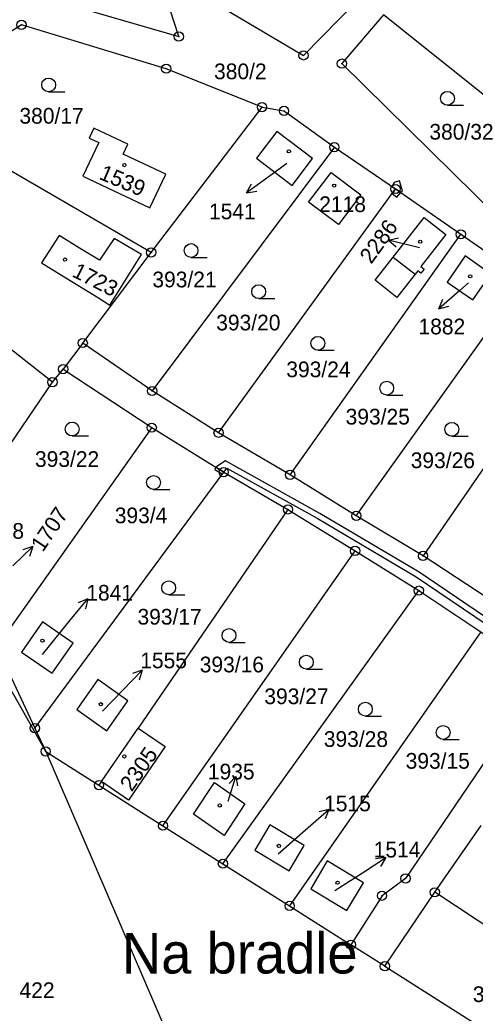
# Model space of a CAD drawing. Extents: x -680203 to -673936, y -1102717 to -1093650.
# Drawn here: x -679915.5 to -679866.3, y -1098047.4 to -1097939.8 of the extents above; entities that cross this region are included whole.
import ezdxf

# ---------------------------------------------------------------- set-up
doc = ezdxf.new("R2010")
doc.units = 0
for name, color, linetype in [('SOxx02xx_Koleje_param další_Popis10', 7, 'Continuous'), ('SOxx02xx_Staničení_Popis10', 7, 'Continuous'), ('SOxxxxxx_Koleje_hlavní_body_Popis10', 7, 'Continuous'), ('SOxxxxxx_Koleje_LN_parametry_Popis10', 7, 'Continuous'), ('SOxxxxxx_Koleje_param další_Popis10', 7, 'Continuous'), ('SOxxxxxx_Osa_bod_P', 7, 'Continuous'), ('SOxxxxxx_Staničení_Popis10', 7, 'Continuous'), ('x_prac', 7, 'Continuous')]:
    doc.layers.add(name, color=color, linetype=linetype)

msp = doc.modelspace()

# ---------------------------------------------------------------- linework, layer by layer
at = {"layer": 'SOxx02xx_Koleje_param další_Popis10'}
for centre, radius in [((-679915.37, -1097940.37), 0.5), ((-679915.37, -1097940.37), 0.0303), ((-679898.34, -1097941.64), 0.5), ((-679898.34, -1097941.64), 0.0303), ((-679884.84, -1097943.68), 0.5), ((-679884.84, -1097943.68), 0.0303), ((-679880.68, -1097944.57), 0.5), ((-679899.7, -1097945.12), 0.5), ((-679899.7, -1097945.12), 0.0303), ((-679880.68, -1097944.57), 0.0303), ((-679889.33, -1097949.28), 0.5), ((-679889.33, -1097949.28), 0.0303), ((-679886.95, -1097949.69), 0.5), ((-679886.95, -1097949.69), 0.0303), ((-679881.5, -1097953.61), 0.5), ((-679881.5, -1097953.61), 0.0303), ((-679874.87, -1097958.14), 0.5), ((-679874.87, -1097958.14), 0.0303), ((-679867.81, -1097963.05), 0.5), ((-679867.81, -1097963.05), 0.0303), ((-679901.33, -1097965.01), 0.5), ((-679901.33, -1097965.01), 0.0303), ((-679908.74, -1097974.82), 0.5), ((-679908.74, -1097974.82), 0.0303), ((-679910.86, -1097977.64), 0.5), ((-679910.86, -1097977.64), 0.0303), ((-679912.02, -1097979.05), 0.5), ((-679912.02, -1097979.05), 0.0303), ((-679901.22, -1097980.01), 0.5), ((-679901.22, -1097980.01), 0.0303), ((-679901.27, -1097983.98), 0.5), ((-679901.27, -1097983.98), 0.0303), ((-679894.03, -1097984.53), 0.5), ((-679894.03, -1097984.53), 0.0303), ((-679893.48, -1097988.79), 0.5), ((-679893.48, -1097988.79), 0.0303), ((-679886.29, -1097989.08), 0.5), ((-679886.29, -1097989.08), 0.0303), ((-679886.52, -1097992.83), 0.5), ((-679886.52, -1097992.83), 0.0303), ((-679879.12, -1097993.52), 0.5), ((-679879.12, -1097993.52), 0.0303), ((-679879.25, -1097997.32), 0.5), ((-679879.25, -1097997.32), 0.0303), ((-679871.9, -1097997.86), 0.5), ((-679871.9, -1097997.86), 0.0303), ((-679872.35, -1098001.62), 0.5), ((-679872.35, -1098001.62), 0.0303), ((-679913.92, -1098016.51), 0.5), ((-679913.92, -1098016.51), 0.0303), ((-679912.75, -1098019.03), 0.5), ((-679912.75, -1098019.03), 0.0303), ((-679906.98, -1098022.68), 0.5), ((-679906.98, -1098022.68), 0.0303), ((-679900.05, -1098027.07), 0.5), ((-679900.05, -1098027.07), 0.0303), ((-679893.56, -1098031.18), 0.5), ((-679893.56, -1098031.18), 0.0303), ((-679873.8, -1098032.78), 0.5), ((-679873.8, -1098032.78), 0.0303), ((-679876.34, -1098034.65), 0.5), ((-679876.34, -1098034.65), 0.0303), ((-679870.63, -1098034.28), 0.5), ((-679870.63, -1098034.28), 0.0303), ((-679886.34, -1098035.75), 0.5), ((-679886.34, -1098035.75), 0.0303), ((-679879.71, -1098039.95), 0.5), ((-679879.71, -1098039.95), 0.0303), ((-679876.03, -1098042.28), 0.5), ((-679876.03, -1098042.28), 0.0303)]:
    msp.add_circle(centre, radius, dxfattribs=at)
at = {"layer": 'SOxx02xx_Staničení_Popis10'}
for p, q in [((-679886.64, -1097955.38), (-679888.57, -1097956.8)), ((-679888.57, -1097956.8), (-679891, -1097958.56)), ((-679891, -1097958.56), (-679890.48, -1097957.57)), ((-679891, -1097958.56), (-679889.89, -1097958.38)), ((-679875.64, -1097963.67), (-679874.55, -1097963.43)), ((-679872.73, -1097964.4), (-679875.64, -1097963.67)), ((-679875.64, -1097963.67), (-679874.79, -1097964.4)), ((-679872.28, -1097964.52), (-679872.73, -1097964.4)), ((-679866.97, -1097968.32), (-679867.92, -1097969.15)), ((-679867.92, -1097969.15), (-679870.19, -1097971.12)), ((-679870.19, -1097971.12), (-679869.76, -1097970.08)), ((-679870.19, -1097971.12), (-679869.1, -1097970.84)), ((-679916.3, -1097998.95), (-679914.14, -1097996.86)), ((-679914.14, -1097996.86), (-679915.21, -1097997.2)), ((-679914.14, -1097996.86), (-679914.51, -1097997.92)), ((-679910.09, -1098004.83), (-679908.2, -1098002.5)), ((-679908.2, -1098002.5), (-679909.22, -1098002.96)), ((-679908.2, -1098002.5), (-679908.44, -1098003.59)), ((-679913.08, -1098008.52), (-679910.09, -1098004.83)), ((-679904.39, -1098012.4), (-679902.31, -1098010.24)), ((-679902.31, -1098010.24), (-679903.36, -1098010.61)), ((-679902.31, -1098010.24), (-679902.64, -1098011.31)), ((-679906.59, -1098014.67), (-679904.39, -1098012.4)), ((-679893, -1098024.43), (-679892.18, -1098021.73)), ((-679892.18, -1098021.73), (-679892.9, -1098022.5)), ((-679892.18, -1098021.73), (-679892, -1098022.77)), ((-679884.34, -1098027.27), (-679882.08, -1098025.3)), ((-679882.08, -1098025.3), (-679883.16, -1098025.58)), ((-679882.08, -1098025.3), (-679882.5, -1098026.34)), ((-679887.59, -1098030.12), (-679884.34, -1098027.27)), ((-679878.44, -1098032.16), (-679875.92, -1098030.53)), ((-679875.92, -1098030.53), (-679877.04, -1098030.65)), ((-679875.92, -1098030.53), (-679876.49, -1098031.49)), ((-679881.45, -1098034.1), (-679878.44, -1098032.16))]:
    msp.add_line(p, q, dxfattribs=at)
at = {"layer": 'SOxxxxxx_Koleje_hlavní_body_Popis10'}
for p, q in [((-679912.43, -1097947.63), (-679910.68, -1097947.63)), ((-679869.26, -1097949.08), (-679867.51, -1097949.08)), ((-679897.01, -1097965.56), (-679895.26, -1097965.56)), ((-679889.69, -1097970.01), (-679887.94, -1097970.01)), ((-679883.28, -1097975.6), (-679881.53, -1097975.6)), ((-679875.83, -1097980.46), (-679874.08, -1097980.46)), ((-679909.88, -1097984.88), (-679908.13, -1097984.88)), ((-679868.78, -1097984.91), (-679867.03, -1097984.91)), ((-679901.07, -1097990.67), (-679899.32, -1097990.67)), ((-679899.43, -1098002.07), (-679897.68, -1098002.07)), ((-679892.9, -1098007.22), (-679891.15, -1098007.22)), ((-679884.53, -1098010.11), (-679882.78, -1098010.11)), ((-679878.14, -1098015.21), (-679876.39, -1098015.21)), ((-679869.72, -1098017.72), (-679867.97, -1098017.72))]:
    msp.add_line(p, q, dxfattribs=at)
for centre in [(-679912.43, -1097946.88), (-679869.26, -1097948.33), (-679897.01, -1097964.81), (-679889.69, -1097969.26), (-679883.28, -1097974.85), (-679875.83, -1097979.71), (-679909.88, -1097984.13), (-679868.78, -1097984.16), (-679901.07, -1097989.92), (-679899.43, -1098001.32), (-679892.9, -1098006.47), (-679884.53, -1098009.36), (-679878.14, -1098014.46), (-679869.72, -1098016.97)]:
    msp.add_circle(centre, 0.75, dxfattribs=at)
at = {"layer": 'SOxxxxxx_Koleje_LN_parametry_Popis10'}
for points in [[(-679874.44, -1097957.26), (-679875.01, -1097957.43), (-679875.28, -1097957.86), (-679874.87, -1097958.14), (-679874.31, -1097958.53), (-679874.13, -1097958.33)], [(-679874.31, -1097958.53), (-679874.87, -1097958.14), (-679875.23, -1097958.63), (-679874.72, -1097959.02)], [(-679894.45, -1097988.5), (-679893.63, -1097988.99), (-679893.48, -1097988.79), (-679894.34, -1097988.26)], [(-679893.13, -1097988.35), (-679883.36, -1097993.78), (-679872.64, -1098000.12), (-679862.4, -1098007.07), (-679857.66, -1098009.56), (-679855.22, -1098009.36), (-679849.47, -1098001.26), (-679845.19, -1097995.51), (-679844.43, -1097995.85), (-679844.1, -1097995.39), (-679845.39, -1097994.77), (-679849.96, -1098000.91), (-679855.55, -1098008.78), (-679857.54, -1098008.95), (-679862.1, -1098006.55), (-679872.32, -1097999.62), (-679883.07, -1097993.26), (-679893.3, -1097987.57), (-679894.34, -1097988.26), (-679893.48, -1097988.79)]]:
    msp.add_lwpolyline(points, close=True, dxfattribs=at)
at = {"layer": 'SOxxxxxx_Koleje_param další_Popis10'}
for centre in [(-679886.42, -1097954.07), (-679904.23, -1097955.56), (-679881.52, -1097957.78), (-679872.21, -1097963.85), (-679910.66, -1097965.78), (-679866.79, -1097967.6), (-679913.1, -1098007.04), (-679906.78, -1098013.92), (-679904.23, -1098019.57), (-679893.9, -1098024.88), (-679887.5, -1098029.26), (-679881.15, -1098033.24)]:
    msp.add_circle(centre, 0.175, dxfattribs=at)
at = {"layer": 'SOxxxxxx_Staničení_Popis10'}
msp.add_line((-679875.12, -1097965.54), (-679872.76, -1097967.38), dxfattribs=at)
at = {"layer": 'x_prac'}
for p, q in [((-679855.09, -1097956.16), (-679876.19, -1097939.3)), ((-679901.33, -1097965.01), (-679889.33, -1097949.28)), ((-679901.33, -1097965.01), (-679925.61, -1097950.92)), ((-679881.5, -1097953.61), (-679901.22, -1097980.01)), ((-679881.5, -1097953.61), (-679874.87, -1097958.14)), ((-679894.03, -1097984.53), (-679874.87, -1097958.14)), ((-679874.87, -1097958.14), (-679867.81, -1097963.05)), ((-679912.02, -1097979.05), (-679934.54, -1097961.35)), ((-679886.29, -1097989.08), (-679867.81, -1097963.05)), ((-679867.81, -1097963.05), (-679860.84, -1097967.86)), ((-679908.74, -1097974.82), (-679901.33, -1097965.01)), ((-679879.12, -1097993.52), (-679860.84, -1097967.86)), ((-679854.05, -1097971.97), (-679871.9, -1097997.86)), ((-679908.74, -1097974.82), (-679910.86, -1097977.64)), ((-679901.22, -1097980.01), (-679908.74, -1097974.82)), ((-679912.02, -1097979.05), (-679910.86, -1097977.64)), ((-679910.86, -1097977.64), (-679901.27, -1097983.98)), ((-679923.62, -1097996.14), (-679912.02, -1097979.05)), ((-679894.03, -1097984.53), (-679901.22, -1097980.01)), ((-679901.27, -1097983.98), (-679918.05, -1098007.7)), ((-679901.27, -1097983.98), (-679893.48, -1097988.79)), ((-679886.29, -1097989.08), (-679894.03, -1097984.53)), ((-679913.92, -1098016.51), (-679893.48, -1097988.79)), ((-679893.48, -1097988.79), (-679886.52, -1097992.83)), ((-679879.12, -1097993.52), (-679886.29, -1097989.08)), ((-679886.52, -1097992.83), (-679902.75, -1098016.51)), ((-679886.52, -1097992.83), (-679879.25, -1097997.32)), ((-679871.9, -1097997.86), (-679879.12, -1097993.52)), ((-679900.05, -1098027.07), (-679879.25, -1097997.32)), ((-679879.25, -1097997.32), (-679872.35, -1098001.62)), ((-679864.83, -1098002.46), (-679871.9, -1097997.86)), ((-679893.56, -1098031.18), (-679872.35, -1098001.62)), ((-679872.35, -1098001.62), (-679865.64, -1098006.09)), ((-679865.64, -1098006.09), (-679886.34, -1098035.75)), ((-679918.05, -1098007.7), (-679913.92, -1098016.51)), ((-679913.92, -1098016.51), (-679912.75, -1098019.03)), ((-679906.72, -1098022.3), (-679902.75, -1098016.51)), ((-679912.75, -1098019.03), (-679906.98, -1098022.68)), ((-679912.75, -1098019.03), (-679891.01, -1098069.42)), ((-679906.72, -1098022.3), (-679906.98, -1098022.68)), ((-679906.98, -1098022.68), (-679900.05, -1098027.07)), ((-679900.05, -1098027.07), (-679893.56, -1098031.18)), ((-679870.63, -1098034.28), (-679865.59, -1098027.05)), ((-679893.56, -1098031.18), (-679886.34, -1098035.75)), ((-679876.03, -1098042.28), (-679870.63, -1098034.28)), ((-679844.71, -1098051.33), (-679870.63, -1098034.28)), ((-679886.34, -1098035.75), (-679879.71, -1098039.95)), ((-679876.03, -1098042.28), (-679879.71, -1098039.95)), ((-679876.03, -1098042.28), (-679859.91, -1098052.49))]:
    msp.add_line(p, q, dxfattribs=at)
for points in [[(-679916.06, -1097936.49), (-679898.34, -1097941.64), (-679899.31, -1097938.64), (-679913.64, -1097932.02)], [(-679901.97, -1097933.51), (-679884.84, -1097943.68), (-679879.07, -1097937.81)], [(-679876.19, -1097939.3), (-679880.68, -1097944.57), (-679861.45, -1097963.5)], [(-679889.33, -1097949.28), (-679899.7, -1097945.12), (-679915.37, -1097940.37), (-679919.41, -1097942.93), (-679925.61, -1097950.92)], [(-679889.33, -1097949.28), (-679886.95, -1097949.69), (-679886.39, -1097950.09), (-679881.5, -1097953.61)], [(-679904.35, -1097954.37), (-679903.84, -1097953.28), (-679907.52, -1097951.55), (-679908.04, -1097952.63), (-679907, -1097953.12), (-679908.72, -1097956.77), (-679901.48, -1097960.18), (-679899.73, -1097956.55), (-679904.35, -1097954.37)], [(-679887.74, -1097951.93), (-679889.93, -1097954.81), (-679886.05, -1097957.75), (-679883.87, -1097954.86), (-679887.74, -1097951.93)], [(-679884.28, -1097959.58), (-679881.86, -1097956.37), (-679878.64, -1097958.79), (-679881.04, -1097961.99), (-679884.28, -1097959.58)], [(-679912.75, -1098019.03), (-679924.75, -1097997.83), (-679943.92, -1097977.59), (-679948.52, -1097974.03), (-679964.54, -1097961.66), (-679967.83, -1097959.12)], [(-679872.47, -1097967), (-679872.76, -1097967.38), (-679874.73, -1097969.88), (-679877.08, -1097968.02), (-679875.12, -1097965.54), (-679871.76, -1097961.23), (-679869.43, -1097963.08), (-679872.12, -1097966.52), (-679871.76, -1097966.81), (-679872.12, -1097967.27), (-679872.47, -1097967)], [(-679913.19, -1097966.15), (-679911.02, -1097967.48), (-679907.03, -1097969.93), (-679905.8, -1097970.71), (-679902.38, -1097965.22), (-679905.34, -1097963.49), (-679906.93, -1097965.86), (-679909.09, -1097964.54), (-679911.28, -1097963.19), (-679913.19, -1097966.15)], [(-679864.57, -1097967.37), (-679867.32, -1097965.37), (-679869.29, -1097968.24), (-679866.49, -1097970.16), (-679864.57, -1097967.37)], [(-679912.06, -1098010.57), (-679909.79, -1098007.3), (-679913.1, -1098004.99), (-679915.37, -1098008.3), (-679912.06, -1098010.57)], [(-679865.64, -1098006.09), (-679858.8, -1098010.66), (-679873.8, -1098032.78), (-679876.34, -1098034.65), (-679879.71, -1098039.95)], [(-679907.09, -1098011.24), (-679909.37, -1098014.49), (-679906.13, -1098016.79), (-679903.84, -1098013.54), (-679907.09, -1098011.24)], [(-679902.75, -1098016.51), (-679899.83, -1098018.5), (-679903.8, -1098024.29), (-679906.72, -1098022.3)], [(-679891.18, -1098024.7), (-679893.42, -1098028.12), (-679896.73, -1098025.81), (-679894.47, -1098022.41), (-679891.18, -1098024.7)], [(-679884.75, -1098029.22), (-679888.48, -1098026.96), (-679890.11, -1098029.71), (-679886.38, -1098031.97), (-679884.75, -1098029.22)], [(-679878.36, -1098033.24), (-679882.28, -1098030.88), (-679884.06, -1098033.89), (-679880.14, -1098036.24), (-679878.36, -1098033.24)]]:
    msp.add_lwpolyline(points, dxfattribs=at)

# ---------------------------------------------------------------- texts
at = {"layer": 'SOxx02xx_Staničení_Popis10'}
msp.add_text('Na bradle', height=4.4, dxfattribs=at).set_placement((-679904.49, -1098043.07))
at = {"layer": 'SOxxxxxx_Osa_bod_P'}
for s, p in [('380/2', (-679894.52, -1097946.26)), ('380/17', (-679915.59, -1097951.07)), ('380/32', (-679871.21, -1097952.8)), ('2118', (-679883.14, -1097960.64)), ('1541', (-679895.07, -1097961.42)), ('393/21', (-679901.2, -1097968.79)), ('393/20', (-679894.29, -1097973.45)), ('1882', (-679872.39, -1097973.88)), ('393/24', (-679886.7, -1097978.52)), ('393/25', (-679880.28, -1097983.64)), ('393/22', (-679913.91, -1097988.23)), ('393/26', (-679873.23, -1097988.36)), ('393/4', (-679905.27, -1097994.33)), ('1708', (-679920.15, -1097996.01)), ('1841', (-679908.35, -1098002.7)), ('393/17', (-679902.81, -1098005.3)), ('1555', (-679902.51, -1098010.03)), ('393/16', (-679896.07, -1098010.47)), ('393/27', (-679889.08, -1098013.91)), ('393/28', (-679882.64, -1098018.54)), ('393/15', (-679873.78, -1098020.9)), ('1935', (-679895.19, -1098022.06)), ('1515', (-679882.61, -1098025.51)), ('1514', (-679877.24, -1098030.51)), ('422', (-679915.58, -1098045.73)), ('393/5', (-679866.51, -1098046.16))]:
    msp.add_text(s, height=1.7, dxfattribs=at).set_placement(p)
for s, rotation, p in [('1539', 337, (-679907.08, -1097957.02)), ('2286', 54, (-679877.51, -1097966.35)), ('1723', 333, (-679910.01, -1097967.56)), ('1707', 56, (-679913.06, -1097997.53)), ('2305', 55, (-679903.44, -1098023.48))]:
    msp.add_text(s, height=1.7, rotation=rotation, dxfattribs=at).set_placement(p)

doc.saveas('drawing.dxf')
